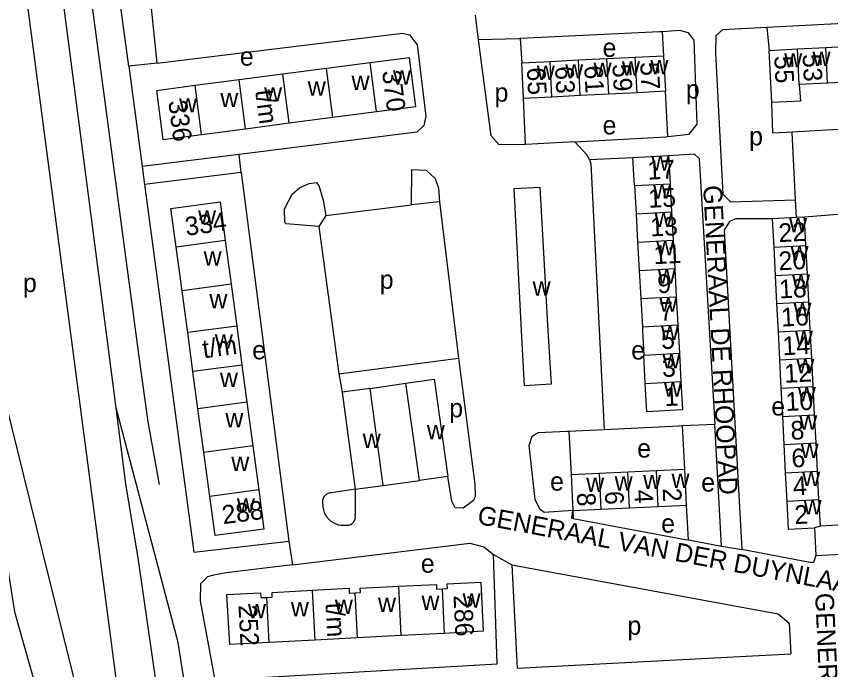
# Model space of a CAD drawing. Extents: x 159294 to 161936, y 384538 to 386517.
# Drawn here: x 161214 to 161388.8, y 385427.1 to 385567.5 of the extents above; entities that cross this region are included whole.
import ezdxf

# ---------------------------------------------------------------- set-up
doc = ezdxf.new("R2010")
doc.units = 0
for name, color, linetype in [('BLT_Basislijn', 7, 'Continuous'), ('BLT_Bebouwing', 7, 'Continuous'), ('BLT_Centroide', 7, 'Continuous'), ('BLT_Huisnummer', 7, 'Continuous'), ('BLT_Huisnummer_ tussenligend', 7, 'Continuous'), ('BLT_Huisnummer_reeks', 7, 'Continuous'), ('BLT_Onderverdeling_panden', 7, 'Continuous'), ('BLT_Straatnaam_verkleind', 7, 'Continuous')]:
    doc.layers.add(name, color=color, linetype=linetype)

msp = doc.modelspace()

# ---------------------------------------------------------------- linework, layer by layer
at = {"layer": 'BLT_Basislijn'}
for p, q in [((161238.1, 385556.72), (161234.17, 385585.77)), ((161313.15, 385562.42), (161312.52, 385567.68)), ((161417.6, 385567.26), (161375.09, 385565.07)), ((161352.64, 385564.16), (161352.93, 385559)), ((161375.09, 385565.07), (161375.57, 385560.14)), ((161322.14, 385562.68), (161322.47, 385557.48)), ((161244.21, 385557.42), (161238.1, 385556.72)), ((161238.1, 385556.72), (161240.96, 385535.22)), ((161353.85, 385541.62), (161353.31, 385551.35)), ((161323.25, 385539.94), (161322.86, 385549.83)), ((161414.48, 385544.45), (161380.51, 385542.61)), ((161381.24, 385528.07), (161380.51, 385542.61)), ((161333.87, 385540.52), (161323.25, 385539.94)), ((161261.79, 385537.76), (161240.96, 385535.22)), ((161262.24, 385533.91), (161261.79, 385537.76)), ((161337.03, 385536.71), (161346.31, 385537.16)), ((161240.96, 385535.22), (161241.49, 385531.31)), ((161262.24, 385533.91), (161241.49, 385531.31)), ((161262.24, 385533.91), (161272.5, 385454.73)), ((161304.78, 385527.61), (161298.81, 385526.99)), ((161304.78, 385527.61), (161308.87, 385494.01)), ((161381.43, 385524.22), (161381.24, 385528.07)), ((161280.42, 385524.68), (161298.81, 385526.99)), ((161280.42, 385524.68), (161278.94, 385522.32)), ((161278.94, 385522.32), (161283.18, 385490.65)), ((161283.18, 385490.65), (161308.87, 385494.01)), ((161283.18, 385490.65), (161283.95, 385486.72)), ((161289.93, 385487.52), (161297.61, 385488.68)), ((161332.56, 385478.34), (161340.17, 385478.72)), ((161332.56, 385478.34), (161333.06, 385469.01)), ((161356.98, 385479.55), (161363.91, 385479.86)), ((161357.49, 385470.16), (161356.98, 385479.55)), ((161365.32, 385453.69), (161363.91, 385479.86)), ((161292.7, 385466.72), (161300.52, 385467.76)), ((161286.73, 385465.92), (161281.66, 385465.11)), ((161286.73, 385465.92), (161286.7, 385460.42)), ((161358.29, 385454.99), (161357.85, 385462.5)), ((161333.42, 385461.35), (161333.51, 385459.58)), ((161272.5, 385454.73), (161273.26, 385449.69)), ((161358.29, 385454.99), (161365.32, 385453.69)), ((161365.32, 385453.69), (161369.72, 385452.93)), ((161316.4, 385451.87), (161320.31, 385449.67))]:
    msp.add_line(p, q, dxfattribs=at)
for points in [[(161235.39, 385483.35), (161216.77, 385627.15), (161205.68, 385715.72)], [(161244.7, 385466.94), (161242.31, 385480.34), (161240.59, 385492.75), (161225.02, 385609.26), (161222.41, 385631.2), (161218.48, 385661.41)], [(161242.47, 385371.34), (161208.94, 385626.35)], [(161244.21, 385557.42), (161242.84, 385570.62), (161290.17, 385576.82), (161291.46, 385576.5), (161292.42, 385572.92), (161293.62, 385571.54), (161296.39, 385571.49), (161299.1, 385574.2), (161299.45, 385576.87), (161297.63, 385588.79)], [(161244.21, 385557.42), (161296.87, 385563.86), (161298.36, 385563.5), (161300.05, 385561.32), (161301.89, 385545.99), (161301.48, 385543.98), (161299.95, 385542.61), (161261.79, 385537.76)], [(161352.64, 385564.16), (161352.07, 385564.12), (161322.14, 385562.68)], [(161353.85, 385541.62), (161358.41, 385542.14), (161360.12, 385544.33), (161359.46, 385562.36), (161358.26, 385563.89), (161356.34, 385564.42), (161352.64, 385564.16)], [(161375.09, 385565.07), (161365.56, 385564.53), (161364.16, 385563.24), (161364.08, 385559.55), (161365.63, 385529.26), (161367.31, 385527.64), (161381.24, 385528.07)], [(161322.14, 385562.68), (161321.82, 385562.66), (161313.15, 385562.42)], [(161323.25, 385539.94), (161323, 385539.92), (161317.6, 385539.85), (161315.87, 385541.76), (161313.15, 385562.42)], [(161380.51, 385542.61), (161376.33, 385542.36), (161376.14, 385548.94)], [(161333.87, 385540.52), (161353.39, 385541.57), (161353.85, 385541.62)], [(161337.03, 385536.71), (161336.46, 385537.7), (161333.87, 385540.52)], [(161353.96, 385537.6), (161359.49, 385537.91), (161360.57, 385536.92), (161363.91, 385479.86)], [(161337.03, 385536.71), (161337.3, 385535.8), (161340.17, 385478.72)], [(161298.81, 385526.99), (161298.85, 385534.57), (161301.97, 385534.41), (161303.87, 385532.62), (161304.63, 385530.52), (161304.78, 385527.61)], [(161241.49, 385531.31), (161252.1, 385452.36), (161272.5, 385454.73)], [(161278.94, 385522.32), (161271.9, 385522.92), (161271.63, 385523.2), (161271.53, 385526.11), (161273.18, 385529.29), (161274.85, 385530.68), (161276.83, 385531.54), (161278.42, 385531.74), (161278.96, 385530.94), (161279.85, 385527.96), (161280.42, 385524.68)], [(161376.24, 385523.95), (161368.43, 385523.95), (161367.06, 385523.41), (161365.95, 385521.5), (161369.72, 385452.93)], [(161397.67, 385458.54), (161393.71, 385524.74), (161392.98, 385525.14), (161383.14, 385524.3)], [(161205.9, 385511.45), (161208.96, 385495.29), (161219.52, 385452.58), (161226.22, 385425.48), (161233.64, 385370.88)], [(161308.87, 385494.01), (161312.4, 385466.97), (161312.45, 385464.32), (161312.13, 385463.46), (161309.91, 385461.85), (161308.16, 385461.89), (161307.43, 385463.36), (161306.59, 385468.6)], [(161251.1, 385417.84), (161248.74, 385432.97), (161235.39, 385483.35)], [(161240.22, 385450.68), (161237.51, 385467.02), (161235.39, 385483.35)], [(161333.42, 385461.35), (161327.3, 385460.88), (161326.36, 385461.64), (161325.33, 385463.68), (161324.06, 385475.3), (161324.7, 385477.26), (161325.97, 385478.11), (161332.23, 385478.33), (161332.56, 385478.34)], [(161340.17, 385478.72), (161356.16, 385479.51), (161356.98, 385479.55)], [(161208.88, 385469.37), (161213.56, 385439.54), (161218.97, 385420.56), (161225.62, 385370.21)], [(161281.66, 385465.11), (161281.27, 385465.09), (161280.9, 385464.99), (161280.55, 385464.82), (161280.24, 385464.58), (161279.99, 385464.28), (161279.81, 385463.93), (161279.7, 385463.56), (161279.67, 385463.17), (161279.72, 385462.79), (161279.75, 385462.68)], [(161279.75, 385462.68), (161279.78, 385462.08), (161279.88, 385461.49), (161280.07, 385460.93), (161280.33, 385460.39), (161280.66, 385459.89), (161281.05, 385459.44), (161281.5, 385459.05), (161281.99, 385458.72), (161282.53, 385458.46), (161283.1, 385458.28), (161283.68, 385458.17), (161284.28, 385458.14), (161284.61, 385458.16)], [(161333.51, 385459.58), (161333.19, 385459.64), (161333.42, 385461.35)], [(161284.61, 385458.16), (161285, 385458.14), (161285.38, 385458.2), (161285.74, 385458.34), (161286.06, 385458.55), (161286.33, 385458.82), (161286.54, 385459.14), (161286.68, 385459.5), (161286.75, 385459.88), (161286.73, 385460.26), (161286.7, 385460.42)], [(161333.51, 385459.58), (161357.57, 385455.12), (161358.29, 385454.99)], [(161273.26, 385449.69), (161311.34, 385454.3), (161314.36, 385453.5), (161316.4, 385451.87)], [(161385.61, 385451.63), (161385.1, 385450.16), (161384.28, 385450.16), (161369.72, 385452.93)], [(161251.99, 385386.99), (161251.93, 385387.84), (161248.55, 385409.33), (161245.42, 385414.4), (161240.22, 385450.68)], [(161253.46, 385441.89), (161256.62, 385424.91), (161317.17, 385428.43), (161316.4, 385451.87)], [(161273.26, 385449.69), (161259.02, 385447.94), (161256, 385447.33), (161255.05, 385447.1), (161253.49, 385445.57), (161253.46, 385441.89)], [(161320.31, 385449.67), (161321.46, 385427.48), (161380.23, 385430.54)], [(161320.31, 385449.67), (161377.5, 385439.14), (161379.88, 385437.12), (161380.23, 385430.54)]]:
    msp.add_lwpolyline(points, dxfattribs=at)
at = {"layer": 'BLT_Bebouwing'}
for p, q in [((161375.57, 385560.14), (161381.65, 385560.46)), ((161381.65, 385560.46), (161387.73, 385560.77)), ((161387.73, 385560.77), (161393.81, 385561.08)), ((161340.74, 385558.39), (161346.84, 385558.7)), ((161346.84, 385558.7), (161352.93, 385559)), ((161352.93, 385559), (161353.31, 385551.35)), ((161376.14, 385548.94), (161375.57, 385560.14)), ((161289.96, 385557.45), (161280.56, 385556.23)), ((161322.47, 385557.48), (161328.56, 385557.78)), ((161322.86, 385549.83), (161322.47, 385557.48)), ((161328.56, 385557.78), (161334.65, 385558.09)), ((161334.65, 385558.09), (161340.74, 385558.39)), ((161280.56, 385556.23), (161271.16, 385555.01)), ((161261.78, 385553.79), (161252.38, 385552.57)), ((161271.16, 385555.01), (161261.78, 385553.79)), ((161394.2, 385553.42), (161388.12, 385553.11)), ((161388.12, 385553.11), (161382.05, 385552.79)), ((161328.95, 385550.13), (161322.86, 385549.83)), ((161335.04, 385550.44), (161328.95, 385550.13)), ((161341.13, 385550.74), (161335.04, 385550.44)), ((161347.22, 385551.05), (161341.13, 385550.74)), ((161353.31, 385551.35), (161347.22, 385551.05)), ((161281.92, 385545.77), (161291.32, 385546.99)), ((161272.52, 385544.55), (161281.92, 385545.77)), ((161253.74, 385542.11), (161263.14, 385543.33)), ((161263.14, 385543.33), (161272.52, 385544.55)), ((161346.31, 385537.16), (161353.96, 385537.6)), ((161353.96, 385537.6), (161354.3, 385531.51)), ((161346.66, 385531.09), (161347, 385525.03)), ((161354.3, 385531.51), (161354.63, 385525.44)), ((161354.63, 385525.44), (161354.97, 385519.38)), ((161347, 385525.03), (161347.34, 385518.96)), ((161381.43, 385524.22), (161376.24, 385523.95)), ((161376.24, 385523.95), (161376.55, 385517.89)), ((161383.14, 385524.3), (161381.43, 385524.22)), ((161383.45, 385518.24), (161383.14, 385524.3)), ((161258.83, 385519.34), (161260.09, 385509.94)), ((161347.34, 385518.96), (161347.69, 385512.9)), ((161354.97, 385519.38), (161355.3, 385513.31)), ((161249.55, 385508.51), (161248.28, 385517.91)), ((161376.55, 385517.89), (161376.87, 385511.83)), ((161383.77, 385512.18), (161383.45, 385518.24)), ((161355.3, 385513.31), (161355.64, 385507.24)), ((161347.69, 385512.9), (161348.03, 385506.83)), ((161376.87, 385511.83), (161377.18, 385505.77)), ((161384.08, 385506.13), (161383.77, 385512.18)), ((161260.09, 385509.94), (161261.29, 385500.95)), ((161348.03, 385506.83), (161348.37, 385500.76)), ((161355.64, 385507.24), (161355.97, 385501.18)), ((161377.18, 385505.77), (161377.49, 385499.71)), ((161384.39, 385500.07), (161384.08, 385506.13)), ((161261.29, 385500.95), (161262.42, 385492.56)), ((161251.89, 385491.15), (161250.76, 385499.53)), ((161377.49, 385499.71), (161377.8, 385493.65)), ((161384.71, 385494.01), (161384.39, 385500.07)), ((161348.99, 385488.62), (161348.68, 385494.69)), ((161356.31, 385495.11), (161356.64, 385489.04)), ((161385.02, 385487.95), (161384.71, 385494.01)), ((161262.42, 385492.56), (161263.49, 385484.57)), ((161377.8, 385493.65), (161378.11, 385487.6)), ((161252.97, 385483.16), (161251.89, 385491.15)), ((161300.52, 385467.76), (161297.61, 385488.68)), ((161289.93, 385487.52), (161283.95, 385486.72)), ((161292.7, 385466.72), (161289.93, 385487.52)), ((161378.11, 385487.6), (161378.42, 385481.54)), ((161385.33, 385481.89), (161385.02, 385487.95)), ((161283.95, 385486.72), (161286.73, 385465.92)), ((161263.49, 385484.57), (161264.74, 385475.18)), ((161254.24, 385473.77), (161252.97, 385483.16)), ((161385.64, 385475.83), (161385.33, 385481.89)), ((161378.42, 385481.54), (161378.73, 385475.48)), ((161264.74, 385475.18), (161266.01, 385465.77)), ((161378.73, 385475.48), (161379.04, 385469.42)), ((161385.96, 385469.77), (161385.64, 385475.83)), ((161255.51, 385464.36), (161254.24, 385473.77)), ((161345.27, 385469.59), (161339.17, 385469.3)), ((161351.38, 385469.87), (161345.27, 385469.59)), ((161357.49, 385470.16), (161351.38, 385469.87)), ((161357.85, 385462.5), (161357.49, 385470.16)), ((161386.27, 385463.71), (161385.96, 385469.77)), ((161306.59, 385468.6), (161300.52, 385467.76)), ((161339.17, 385469.3), (161333.06, 385469.01)), ((161333.06, 385469.01), (161333.42, 385461.35)), ((161379.04, 385469.42), (161379.36, 385463.36)), ((161286.73, 385465.92), (161292.7, 385466.72)), ((161351.74, 385462.21), (161357.85, 385462.5)), ((161333.42, 385461.35), (161339.53, 385461.64)), ((161339.53, 385461.64), (161345.63, 385461.93)), ((161345.63, 385461.93), (161351.74, 385462.21)), ((161385.3, 385457.59), (161385.61, 385451.63)), ((161305.83, 385434.94), (161296.58, 385434.46)), ((161278.12, 385433.49), (161268.2, 385432.97)), ((161287.17, 385433.96), (161278.12, 385433.49)), ((161296.58, 385434.46), (161287.17, 385433.96))]:
    msp.add_line(p, q, dxfattribs=at)
for points in [[(161291.32, 385546.99), (161299.7, 385548.08), (161298.35, 385558.54), (161289.96, 385557.45)], [(161252.38, 385552.57), (161244.08, 385551.49), (161245.44, 385541.03), (161253.74, 385542.11)], [(161382.05, 385552.79), (161382.29, 385549.25), (161376.14, 385548.94)], [(161346.66, 385531.09), (161346.6, 385532.17), (161346.31, 385537.16)], [(161328.1, 385500), (161328.75, 385488.46), (161323.07, 385488.13), (161322.62, 385495.96), (161322.41, 385500), (161320.85, 385530.47), (161326.36, 385530.77), (161328.1, 385500)], [(161248.28, 385517.91), (161247.16, 385526.18), (161257.72, 385527.61), (161258.83, 385519.34)], [(161250.76, 385499.53), (161250.7, 385500), (161249.55, 385508.51)], [(161355.97, 385501.18), (161356.04, 385500), (161356.31, 385495.11)], [(161348.37, 385500.76), (161348.42, 385500), (161348.68, 385494.69)], [(161297.61, 385488.68), (161303.67, 385489.53), (161306.59, 385468.6)], [(161356.64, 385489.04), (161356.98, 385482.94), (161349.29, 385482.55), (161348.99, 385488.62)], [(161266.01, 385465.77), (161267.14, 385457.34), (161256.64, 385455.93), (161255.51, 385464.36)], [(161379.36, 385463.36), (161379.67, 385457.29), (161385.3, 385457.59)], [(161386.57, 385457.97), (161386.38, 385461.62), (161386.27, 385463.71)], [(161385.61, 385451.63), (161397.99, 385452.27), (161397.67, 385458.54)], [(161397.67, 385458.54), (161392.68, 385458.29), (161386.57, 385457.97)], [(161286.65, 385443.65), (161287.85, 385443.71), (161287.8, 385444.64), (161296.06, 385445.04)], [(161296.06, 385445.04), (161304.15, 385445.44), (161304.2, 385444.45), (161305.36, 385444.51)], [(161305.36, 385444.51), (161306.53, 385444.57), (161306.48, 385445.55), (161313.66, 385445.9), (161314.16, 385435.38), (161305.83, 385434.94)], [(161268.2, 385432.97), (161259.78, 385432.53), (161259.2, 385443.29), (161266.4, 385443.67), (161266.46, 385442.61), (161267.69, 385442.67)], [(161267.69, 385442.67), (161268.92, 385442.74), (161268.87, 385443.74), (161277.55, 385444.21)], [(161277.55, 385444.21), (161285.4, 385444.62), (161285.45, 385443.59), (161286.65, 385443.65)]]:
    msp.add_lwpolyline(points, dxfattribs=at)
at = {"layer": 'BLT_Onderverdeling_panden'}
for p, q in [((161382.05, 385552.79), (161381.65, 385560.46)), ((161388.12, 385553.11), (161387.73, 385560.77)), ((161347.22, 385551.05), (161346.84, 385558.7)), ((161291.32, 385546.99), (161289.96, 385557.45)), ((161328.95, 385550.13), (161328.56, 385557.78)), ((161335.04, 385550.44), (161334.65, 385558.09)), ((161341.13, 385550.74), (161340.74, 385558.39)), ((161281.92, 385545.77), (161280.56, 385556.23)), ((161263.14, 385543.33), (161261.78, 385553.79)), ((161272.52, 385544.55), (161271.16, 385555.01)), ((161253.74, 385542.11), (161252.38, 385552.57)), ((161346.66, 385531.09), (161354.3, 385531.51)), ((161347, 385525.03), (161354.63, 385525.44)), ((161258.83, 385519.34), (161248.28, 385517.91)), ((161347.34, 385518.96), (161354.97, 385519.38)), ((161376.55, 385517.89), (161383.45, 385518.24)), ((161347.69, 385512.9), (161355.3, 385513.31)), ((161376.87, 385511.83), (161383.77, 385512.18)), ((161260.09, 385509.94), (161249.55, 385508.51)), ((161348.03, 385506.83), (161355.64, 385507.24)), ((161377.18, 385505.77), (161384.08, 385506.13)), ((161261.29, 385500.95), (161250.76, 385499.53)), ((161348.37, 385500.76), (161355.97, 385501.18)), ((161377.49, 385499.71), (161384.39, 385500.07)), ((161348.68, 385494.69), (161356.31, 385495.11)), ((161377.8, 385493.65), (161384.71, 385494.01)), ((161262.42, 385492.56), (161251.89, 385491.15)), ((161348.99, 385488.62), (161356.64, 385489.04)), ((161378.11, 385487.6), (161385.02, 385487.95)), ((161263.49, 385484.57), (161252.97, 385483.16)), ((161378.42, 385481.54), (161385.33, 385481.89)), ((161264.74, 385475.18), (161254.24, 385473.77)), ((161378.73, 385475.48), (161385.64, 385475.83)), ((161345.63, 385461.93), (161345.27, 385469.59)), ((161351.74, 385462.21), (161351.38, 385469.87)), ((161379.04, 385469.42), (161385.96, 385469.77)), ((161339.53, 385461.64), (161339.17, 385469.3)), ((161266.01, 385465.77), (161255.51, 385464.36)), ((161379.36, 385463.36), (161386.27, 385463.71)), ((161386.57, 385457.97), (161385.3, 385457.59)), ((161296.58, 385434.46), (161296.06, 385445.04)), ((161278.12, 385433.49), (161277.55, 385444.21)), ((161286.65, 385443.65), (161287.17, 385433.96)), ((161305.36, 385444.51), (161305.83, 385434.94)), ((161267.69, 385442.67), (161268.2, 385432.97))]:
    msp.add_line(p, q, dxfattribs=at)

# ---------------------------------------------------------------- texts
at = {"layer": 'BLT_Centroide'}
for s, p in [('e', (161339.82, 385558.74)), ('e', (161261.96, 385556.86)), ('w', (161378.81, 385556.47)), ('w', (161384.89, 385556.78)), ('w', (161325.7, 385553.8)), ('w', (161331.8, 385554.11)), ('w', (161337.89, 385554.42)), ('w', (161343.98, 385554.72)), ('w', (161350.08, 385555.02)), ('w', (161294.83, 385552.77)), ('w', (161276.53, 385550.39)), ('w', (161285.94, 385551.61)), ('w', (161267.16, 385549.17)), ('p', (161316.63, 385549.12)), ('p', (161357.69, 385549.8)), ('w', (161248.91, 385546.81)), ('w', (161257.77, 385547.95)), ('e', (161339.82, 385542.1)), ('p', (161371.28, 385539.74)), ('w', (161350.3, 385534.34)), ('w', (161350.65, 385528.28)), ('w', (161252.99, 385522.75)), ('w', (161350.98, 385522.19)), ('w', (161379.85, 385521.09)), ('w', (161351.32, 385516.12)), ('w', (161254.18, 385513.94)), ('w', (161380.16, 385515.03)), ('p', (161291.98, 385508.93)), ('w', (161351.66, 385510.06)), ('w', (161380.48, 385508.97)), ('p', (161215.4, 385508.24)), ('w', (161324.8, 385507.45)), ('w', (161255.42, 385504.72)), ('w', (161352, 385504)), ('w', (161380.79, 385502.91)), ('w', (161352.34, 385497.94)), ('w', (161381.1, 385496.88)), ('w', (161256.59, 385496.06)), ('e', (161264.61, 385493.79)), ('e', (161345.96, 385493.76)), ('w', (161352.66, 385491.88)), ('w', (161381.41, 385490.81)), ('w', (161257.69, 385487.84)), ('w', (161352.97, 385485.78)), ('w', (161381.72, 385484.75)), ('p', (161306.9, 385481.34)), ('e', (161376.03, 385481.72)), ('w', (161258.85, 385479.16)), ('w', (161382.03, 385478.69)), ('w', (161302.09, 385476.64)), ('w', (161288.33, 385474.72)), ('e', (161347.24, 385472.69)), ('w', (161382.34, 385472.62)), ('w', (161260.12, 385469.78)), ('w', (161382.66, 385466.56)), ('e', (161328.55, 385465.59)), ('w', (161336.3, 385465.33)), ('w', (161342.41, 385465.61)), ('w', (161348.52, 385465.91)), ('w', (161354.61, 385466.19)), ('e', (161360.99, 385465.38)), ('w', (161261.33, 385460.84)), ('w', (161382.97, 385460.5)), ('e', (161352.4, 385456.57)), ('e', (161300.8, 385447.96)), ('w', (161309.77, 385440.44)), ('w', (161272.91, 385438.59)), ('w', (161282.36, 385439.09)), ('w', (161291.61, 385439.5)), ('w', (161300.95, 385439.98)), ('w', (161263.7, 385438.14)), ('p', (161345.16, 385434.62))]:
    msp.add_text(s, height=4, dxfattribs=at).set_placement(p)
at = {"layer": 'BLT_Huisnummer'}
for s, rotation, p in [('55', 272.9441, (161376.66, 385558.91)), ('57', 272.8661, (161347.89, 385557.56)), ('65', 272.8661, (161323.56, 385556.41)), ('61', 272.8661, (161335.88, 385556.82)), ('17', 2.8829, (161349.53, 385532.37)), ('13', 2.8829, (161350.11, 385520.18)), ('22', 2.976, (161377.67, 385518.95)), ('9', 2.8829, (161351.65, 385507.97)), ('18', 2.976, (161377.78, 385506.86)), ('5', 2.8829, (161352.45, 385495.99)), ('14', 2.976, (161378.52, 385494.65)), ('1', 2.8829, (161353.2, 385483.74)), ('10', 2.976, (161379.18, 385482.68)), ('6', 2.976, (161380.45, 385470.54)), ('8', 272.6904, (161334.27, 385465.09)), ('2', 272.6904, (161352.71, 385466.07)), ('2', 2.976, (161381.08, 385458.39))]:
    msp.add_text(s, height=4, rotation=rotation, dxfattribs=at).set_placement(p)
at = {"layer": 'BLT_Huisnummer_ tussenligend'}
for s, rotation, p in [('53', 272.9441, (161382.74, 385559.3)), ('59', 272.8661, (161341.93, 385557.16)), ('63', 272.8661, (161329.61, 385556.68)), ('15', 2.8829, (161349.71, 385526.33)), ('11', 2.8829, (161350.85, 385514.21)), ('20', 2.976, (161377.68, 385512.9)), ('7', 2.8829, (161352.14, 385502.05)), ('16', 2.976, (161378.23, 385500.81)), ('3', 2.8829, (161352.65, 385489.97)), ('12', 2.976, (161378.9, 385488.74)), ('8', 2.976, (161380.26, 385476.49)), ('4', 2.976, (161380.77, 385464.55)), ('6', 272.6904, (161340.3, 385465.44)), ('4', 272.6904, (161346.6, 385465.74))]:
    msp.add_text(s, height=4, rotation=rotation, dxfattribs=at).set_placement(p)
at = {"layer": 'BLT_Huisnummer_reeks'}
for s, rotation, p in [('370', 277.4068, (161292.47, 385555.64)), ('t/m', 277.3924, (161265.24, 385551.49)), ('336', 277.3932, (161246.59, 385549.21)), ('334', 7.6946, (161250.47, 385520.3)), ('t/m', 7.631, (161254.19, 385494.01)), ('288', 7.6318, (161258.4, 385458.37)), ('t/m', 273.0553, (161280.34, 385441.44)), ('286', 272.7994, (161307.81, 385443.11)), ('252', 273.0542, (161261.65, 385441))]:
    msp.add_text(s, height=4, rotation=rotation, dxfattribs=at).set_placement(p)
at = {"layer": 'BLT_Straatnaam_verkleind'}
for s, height, rotation, p in [('GENERAAL DE RHOOPAD', 4, 272.9965, (161361.41, 385531.08)), ('GENERAAL VAN DER DUYNLAAN', 4, 349.3851, (161312.75, 385458.49)), ('GENERAAL DE FAMARSLAAN', 3.9999, 272.5376, (161385.44, 385443.55))]:
    msp.add_text(s, height=height, rotation=rotation, dxfattribs=at).set_placement(p)

doc.saveas('drawing.dxf')
